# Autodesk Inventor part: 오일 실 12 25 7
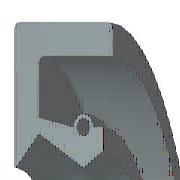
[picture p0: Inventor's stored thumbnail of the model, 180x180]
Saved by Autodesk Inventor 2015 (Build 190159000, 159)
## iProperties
IsCustomPart: 1
Created: 2012-02
Part Number: 오일 실 12 25 7
Material: 고무
Description: 오일-실
Document SubType Name: Modeling
Standard: KS B 2804
Designer: test
Standards Organization: KS
Language: ko-KR
Size Designation: D - 12 25 7
Categories: <MemberInstance><Categories><Category DisplayName="샤프트 부품" InternalName="7f7aeb1f-a693-4053-b835-cee3144e0d98" Mnemonic="SHFT"><Category DisplayName="실링" Intern
Density: 0.93 g/cm^3
Appearance: 고무 - 검은색 - 버전 1.1
Author: test
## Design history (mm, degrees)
revolve "본체" stored, may be unused: angle "d17" = 90 deg
revolve "스프링1" stored, may be unused: angle "d18" = 90 deg
body "Solid1"
sketch "스케치1"
  geometry: L1 (0, 12.5)-(7, 12.5); L2 (7, 10.75)-(1.75, 10.75); L3 (1.75, 7.75)-(4.9, 6); L4 (4.9, 6)-(0, 6); L5 (0, 0)-(9.586, 0) reference; L6 (4.9, 6)-(6.3, 6.875); L7 (0, 18)-(0, -3) reference; L8 (-1.941, 0)-(11.507, 0) reference; L9 (4.2, 8.1)-(1.75, 8.59); L10 (1.75, 8.59)-(1.75, 10.75); L11 (0, 12.5)-(0, 6.088); L12 (4.9, 6)-(0, 6); L13 (1.75, 7.75)-(0.152, 6.028); L14 (7, 12.5)-(7, 10.75); L15 (5.6, 8.1)-(6.3, 8.1); L16 (6.3, 8.1)-(6.3, 6.875); C1 r 0.455 at (4.9, 8.1); A1 r 0.7 centre (4.9, 8.1) between (5.6, 8.1) and (4.2, 8.1); A2 r 0.088 centre (0.088, 6.088) between (0, 6.088) and (0.152, 6.028); 1 further point
  constraints: 28 end point, 5 horizontal alignment, 5 point on line, 4 point on circle, 4 vertical alignment, 3 centre point, 3 tangent, 2 collinear, 2 horizontal, 2 perpendicular, 1 coincident, 1 parallel
  dimensions: "d0" = 25 diameter of L1 L5 (= SD2); "d1" = 1.75 distance of L1.end L2.start (= SD); "d2" = 0.91 diameter of C1 (= SPDI); "d3" = 1.4 diameter of A1 (= SPDA); "d4" = 12 diameter of L3.end L5 (= NND); "d5" = 15.5 diameter of L3.start L5 (= TKDM); "d7" = 17.18 diameter of L9.end L5 (= TKDM + 0.24 x SWDT); "d8" = 1.75 distance between parallel lines of L11 L10 (= SD); "d9" = 4.9 distance from line of L11 C1.centre (= SPDST); "d10" = 16.2 diameter of C1.centre L5 (= HLDM); "d11" = 0.0875 radius of A2 (= 0.25 x LAB); "d12" = 6.3 distance between parallel lines of L11 L16 (= SDI); "d13" = 13.75 diameter of L6.end L5 (= ABDM); "d14" = 7 distance from line of L11 L1.end (= SWDT)
fillet "모깎기1" dims "d6" = 0.3 (= RR)
other parameters: "SD2" = 25 [user parameter; used in 1 equation term], "SWDT" = 7 [user parameter; used in 2 equation terms], "RR" = 0.3 [user parameter; used in 1 equation term], "SD" = 1.75 [user parameter; used in 2 equation terms], "NND" = 12 [user parameter; used in 1 equation term], "SPDA" = 1.4 [user parameter; used in 1 equation term], "SPDI" = 0.91 [user parameter; used in 1 equation term], "TKDM" = 15.5 [user parameter; used in 2 equation terms], "HLDM" = 16.2 [user parameter; used in 1 equation term], "ABDM" = 13.75 [user parameter; used in 1 equation term], "SDI" = 6.3 [user parameter; used in 1 equation term], "SPDST" = 4.9 [user parameter; used in 1 equation term], "LAB" = 0.35 [user parameter; used in 1 equation term], "d15" = 0, "d16" = 0, "d19" = 0
